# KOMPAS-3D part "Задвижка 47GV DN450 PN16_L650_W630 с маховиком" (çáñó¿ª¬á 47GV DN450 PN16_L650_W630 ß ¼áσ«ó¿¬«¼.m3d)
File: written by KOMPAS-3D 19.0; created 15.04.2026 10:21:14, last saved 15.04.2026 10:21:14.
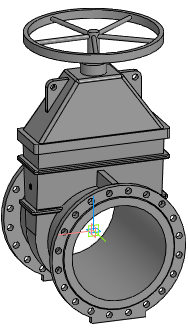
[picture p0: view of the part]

Document properties: Автор: Евгений; Полное имя файла: Z:\3.Личные\kachalov\3d для проектировщиков\2.1 Тип 47GV, 47GV.Z\Задвижка 47GV_DN40-DN600\stp_Задвижка 47GV\Задвижка 47GV DN450 PN16_L650_W630 с маховиком.m3d

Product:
- Part/product: Задвижка 47GV DN450 PN16_L650_W630 с маховиком

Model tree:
1. Операция без истории:1  (labels: Задвижка 47GV DN450 PN16_L650_W630 с маховиком)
